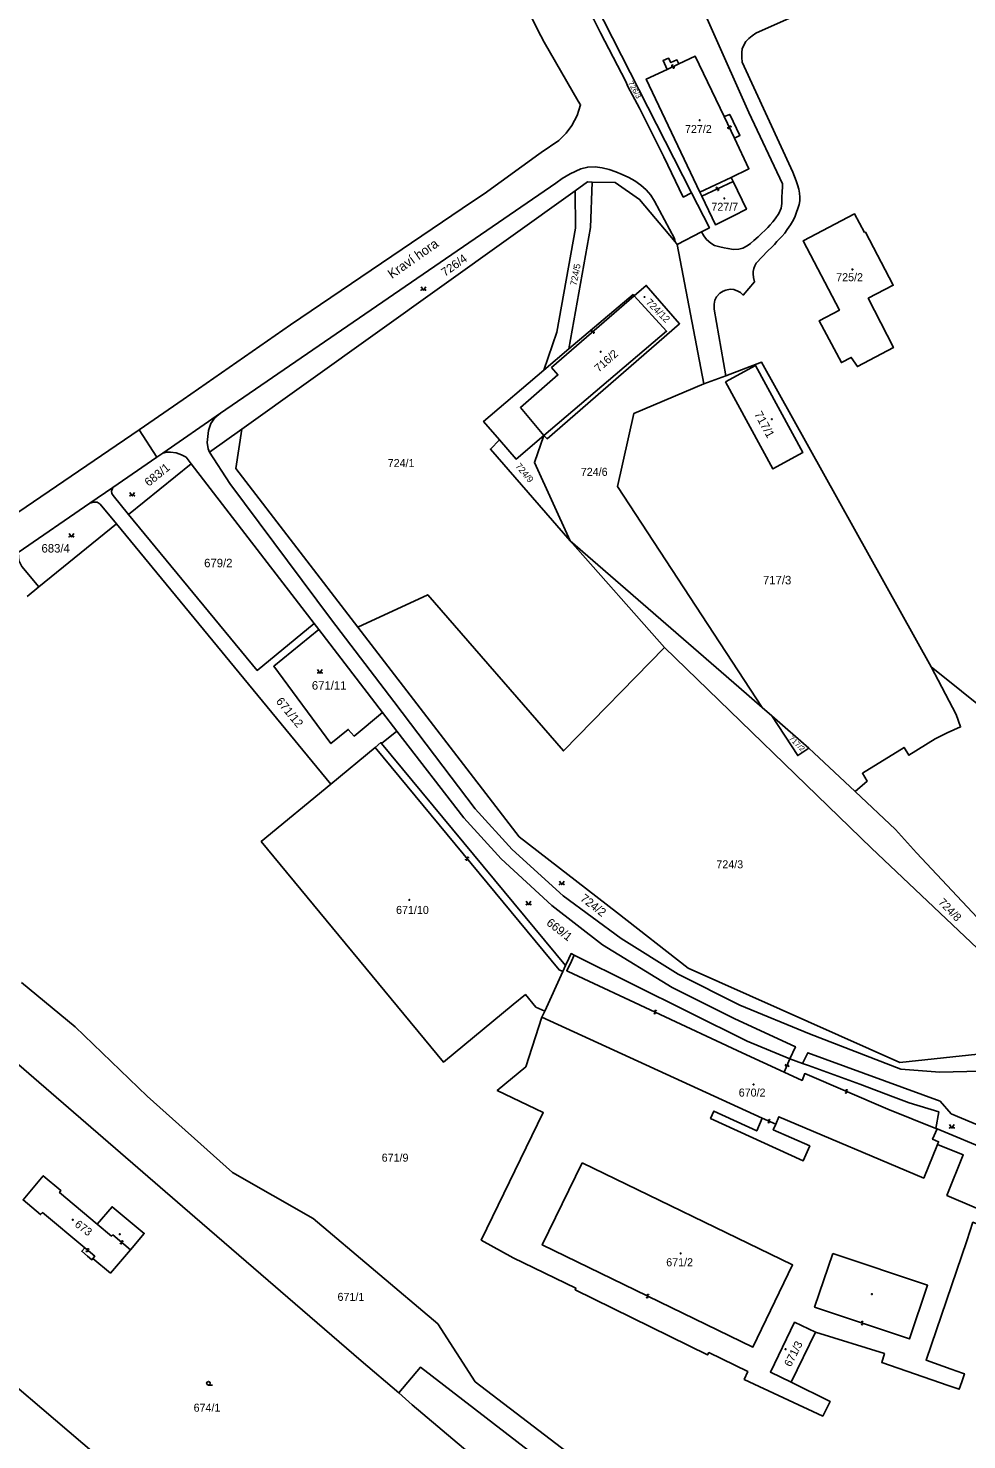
# Model space of a CAD drawing. Extents: x -600391 to -599491, y -1160176 to -1159402.
# Drawn here: x -599792.2 to -599592.8, y -1159973.1 to -1159673.2 of the extents above; entities that cross this region are included whole.
import ezdxf

# ---------------------------------------------------------------- set-up
doc = ezdxf.new("R2010")
doc.units = 0
for name, color, linetype in [('Level 1', 7, 'Continuous'), ('Level 11', 7, 'Continuous'), ('Level 13', 7, 'Continuous'), ('Level 3', 7, 'Continuous'), ('Level 4', 7, 'Continuous'), ('Level 5', 7, 'Continuous')]:
    doc.layers.add(name, color=color, linetype=linetype)

msp = doc.modelspace()

# ---------------------------------------------------------------- linework, layer by layer
at = {"layer": 'Level 1'}
for points in [[(-599712.64, -1159616.57), (-599683.31, -1159674.79), (-599682.57, -1159676.17), (-599675.38, -1159688.67), (-599674.87, -1159689.47), (-599675.56, -1159691.73), (-599676.7, -1159693.85), (-599677.93, -1159695.48), (-599679.49, -1159697.03), (-599683.21, -1159699.58), (-599683.7, -1159699.97), (-599695.31, -1159708.39), (-599697.8, -1159710.05), (-599736.49, -1159736.2), (-599759.29, -1159752.12), (-599768.64, -1159758.53)], [(-599649.16, -1159716.47), (-599648.64, -1159717.29), (-599648.12, -1159718.07), (-599647.22, -1159718.86), (-599646.41, -1159719.36), (-599645.26, -1159719.67), (-599644.38, -1159719.86), (-599643.57, -1159719.98), (-599642.37, -1159720.22), (-599641.27, -1159720.17), (-599640.39, -1159719.92), (-599639.44, -1159719.42), (-599638.77, -1159718.92), (-599638.02, -1159718.29), (-599637.14, -1159717.53), (-599636.39, -1159716.82), (-599635.66, -1159716.1), (-599635.11, -1159715.54), (-599634.57, -1159714.98), (-599634.02, -1159714.36), (-599633.49, -1159713.72), (-599632.75, -1159712.6), (-599632.27, -1159711.41), (-599632.11, -1159710.47), (-599632.07, -1159709.22), (-599632, -1159707.84), (-599631.98, -1159707.06), (-599631.96, -1159706.29), (-599639.09, -1159691.09), (-599669.39, -1159622.91)], [(-599538.78, -1159630.11), (-599637.64, -1159674.26), (-599638.39, -1159674.81), (-599639.14, -1159675.36), (-599639.73, -1159676.01), (-599640.17, -1159676.81), (-599640.5, -1159677.58), (-599640.62, -1159678.37), (-599640.57, -1159679.39), (-599640.53, -1159680.42), (-599629.79, -1159703.81), (-599629.44, -1159704.7), (-599629.09, -1159705.59), (-599628.77, -1159706.48), (-599628.49, -1159707.4), (-599628.33, -1159708.24), (-599628.28, -1159709.09), (-599628.31, -1159709.86), (-599628.44, -1159710.64), (-599628.68, -1159711.47), (-599628.96, -1159712.28), (-599629.28, -1159713.1), (-599629.64, -1159713.91), (-599630.24, -1159714.98), (-599630.95, -1159715.99), (-599631.49, -1159716.72), (-599632.07, -1159717.42), (-599632.61, -1159717.98), (-599633.15, -1159718.54), (-599633.68, -1159719.15), (-599634.23, -1159719.73), (-599635.09, -1159720.48), (-599637.52, -1159723.1), (-599637.85, -1159723.69), (-599638.03, -1159724.24), (-599638.17, -1159724.9), (-599638.18, -1159725.4), (-599638.12, -1159726.14), (-599637.92, -1159727.1), (-599640.3, -1159729.89), (-599640.89, -1159729.34), (-599641.46, -1159729.04), (-599642.32, -1159728.73), (-599643.1, -1159728.65), (-599643.99, -1159728.84), (-599644.57, -1159729.06), (-599645.27, -1159729.51), (-599645.96, -1159730.28), (-599646.32, -1159730.97), (-599646.49, -1159731.85), (-599646.45, -1159732.9), (-599644, -1159747.03)], [(-599677.39, -1159656.98), (-599676.98, -1159659.66), (-599676.42, -1159662.83), (-599672.04, -1159671.33), (-599670.64, -1159674.17), (-599665.22, -1159684.53), (-599664.79, -1159685.6), (-599662.32, -1159690.16), (-599660.1, -1159694.72), (-599657.17, -1159700.54), (-599653.04, -1159709.06), (-599651.27, -1159708.2)], [(-599651.27, -1159708.2), (-599677.39, -1159656.98)], [(-599656.49, -1159681.96), (-599657.33, -1159680.07), (-599656.21, -1159679.54), (-599655.68, -1159680.51), (-599654.38, -1159679.93), (-599653.96, -1159680.76)], [(-599653.96, -1159680.76), (-599650.51, -1159679.17), (-599644.33, -1159691.98)], [(-599656.49, -1159681.96), (-599660.91, -1159684.01), (-599649.52, -1159708)], [(-599644.33, -1159691.98), (-599643.16, -1159691.5), (-599641.01, -1159695.98), (-599642.13, -1159696.53)], [(-599642.13, -1159696.53), (-599639.11, -1159703.04), (-599642.85, -1159704.89)], [(-599751.37, -1159755.02), (-599680.09, -1159706.1), (-599678.78, -1159705.16), (-599677.07, -1159704.13), (-599674.81, -1159703.05), (-599673.32, -1159702.69), (-599671.79, -1159702.68), (-599670.28, -1159702.87), (-599668.82, -1159703.24), (-599667.39, -1159703.7), (-599666, -1159704.26), (-599664.61, -1159704.91), (-599663.32, -1159705.65), (-599662.08, -1159706.53), (-599660.95, -1159707.54), (-599659.95, -1159708.68), (-599659.16, -1159709.97), (-599654.92, -1159717.89), (-599654.76, -1159718.59)], [(-599642.85, -1159704.89), (-599649.52, -1159708)], [(-599642.85, -1159704.89), (-599642.44, -1159705.8)], [(-599746.8, -1159758.36), (-599676.04, -1159707.75)], [(-599676.04, -1159707.75), (-599675.94, -1159715.66), (-599679.93, -1159737.8), (-599682.66, -1159745.87)], [(-599677.33, -1159741.35), (-599672.72, -1159715.52), (-599672.39, -1159705.88)], [(-599672.39, -1159705.88), (-599673.38, -1159705.85), (-599676.04, -1159707.75)], [(-599654.76, -1159718.59), (-599662.33, -1159709.57), (-599667.52, -1159706), (-599672.39, -1159705.88)], [(-599642.44, -1159705.8), (-599639.61, -1159711.67), (-599642.39, -1159713.07), (-599646.21, -1159714.96), (-599649.08, -1159708.89)], [(-599649.16, -1159716.47), (-599647.5, -1159715.59), (-599651.27, -1159708.2)], [(-599649.08, -1159708.89), (-599649.52, -1159708)], [(-599614.56, -1159716.63), (-599614.34, -1159716.51), (-599608.43, -1159727.8), (-599613.75, -1159730.59), (-599608.39, -1159741.06), (-599616.04, -1159745.09), (-599617.37, -1159743.13), (-599619.45, -1159744.23), (-599624.14, -1159735.34), (-599619.87, -1159733.09), (-599627.57, -1159718.38), (-599616.64, -1159712.65), (-599614.56, -1159716.63)], [(-599649.16, -1159716.47), (-599654.31, -1159719.13)], [(-599654.76, -1159718.59), (-599654.31, -1159719.13)], [(-599654.31, -1159719.13), (-599648.64, -1159748.77)], [(-599663.47, -1159730.07), (-599660.9, -1159727.84), (-599653.83, -1159735.98), (-599681.95, -1159760.43), (-599682.65, -1159759.73)], [(-599682.65, -1159759.73), (-599656.58, -1159737.57), (-599663.47, -1159730.07)], [(-599677.33, -1159741.35), (-599663.72, -1159729.8), (-599663.47, -1159730.07)], [(-599682.66, -1159745.87), (-599677.33, -1159741.35)], [(-599682.66, -1159745.87), (-599695.47, -1159756.75), (-599692.07, -1159760.68)], [(-599644.09, -1159748.36), (-599633.99, -1159766.83), (-599627.64, -1159763.35), (-599637.73, -1159744.88), (-599644.09, -1159748.36)], [(-599600.38, -1159808.9), (-599636.39, -1159744.16), (-599644, -1159747.03)], [(-599648.64, -1159748.77), (-599663.55, -1159755.08), (-599667.02, -1159770.59), (-599636.31, -1159817.5)], [(-599648.64, -1159748.77), (-599644, -1159747.03)], [(-599763.62, -1159763.5), (-599751.37, -1159755.02)], [(-599751.37, -1159755.02), (-599752.54, -1159756), (-599753.45, -1159757.22), (-599753.94, -1159758.67), (-599754.18, -1159761.21), (-599754.01, -1159762.59), (-599753.71, -1159763.28)], [(-599768.64, -1159758.53), (-599823.19, -1159795.64), (-599855.6, -1159818.02), (-599902.81, -1159850.42), (-599908.7, -1159854.48)], [(-599764.9, -1159764.36), (-599768.64, -1159758.53)], [(-599753.71, -1159763.28), (-599746.8, -1159758.36)], [(-599746.8, -1159758.36), (-599748.08, -1159766.75), (-599722.17, -1159800.44)], [(-599692.07, -1159760.68), (-599694.03, -1159762.63), (-599677.09, -1159782.15)], [(-599682.65, -1159759.73), (-599688.55, -1159764.75), (-599692.07, -1159760.68)], [(-599677.09, -1159782.15), (-599684.68, -1159765.47), (-599682.65, -1159759.73)], [(-599774.25, -1159770.78), (-599764.9, -1159764.36)], [(-599763.62, -1159763.5), (-599764.9, -1159764.36)], [(-599757.61, -1159765.75), (-599758.68, -1159764.37), (-599759.64, -1159763.82), (-599760.79, -1159763.44), (-599762, -1159763.26), (-599762.83, -1159763.28), (-599763.62, -1159763.5)], [(-599753.71, -1159763.28), (-599749.4, -1159769.94), (-599727.76, -1159798.93), (-599714.51, -1159816.26), (-599697.25, -1159839.07), (-599689.39, -1159847.67), (-599678.59, -1159857.57), (-599666.21, -1159866.59), (-599654.11, -1159874.19), (-599640.99, -1159880.78), (-599626.25, -1159886.88), (-599606.79, -1159894.4), (-599598.5, -1159895.01), (-599584.26, -1159894.68), (-599569.62, -1159897.92), (-599566.09, -1159903.38), (-599555.13, -1159908.18), (-599532.12, -1159913.92), (-599490.77, -1159920.87)], [(-599770.9, -1159776.55), (-599757.61, -1159765.75)], [(-599757.61, -1159765.75), (-599731.47, -1159799.69)], [(-599779.15, -1159774.14), (-599774.25, -1159770.78)], [(-599774.25, -1159770.78), (-599774.51, -1159771.53), (-599774.48, -1159772.05), (-599774.18, -1159772.51), (-599770.9, -1159776.55)], [(-599773.45, -1159778.52), (-599776.9, -1159774.35), (-599777.59, -1159773.93), (-599778.36, -1159773.87), (-599779.15, -1159774.14)], [(-599794.35, -1159784.57), (-599779.15, -1159774.14)], [(-599731.47, -1159799.69), (-599743.54, -1159809.66), (-599770.9, -1159776.55)], [(-599789.93, -1159791.92), (-599773.45, -1159778.52)], [(-599773.45, -1159778.52), (-599727.9, -1159833.79)], [(-599677.09, -1159782.15), (-599641.21, -1159813.22), (-599636.31, -1159817.5)], [(-599677.09, -1159782.15), (-599657.03, -1159804.78)], [(-599794.35, -1159784.57), (-599794.24, -1159786.26), (-599793.56, -1159787.6), (-599789.93, -1159791.92)], [(-599789.93, -1159791.92), (-599792.44, -1159793.96)], [(-599722.17, -1159800.44), (-599707.32, -1159793.57), (-599678.49, -1159826.77), (-599657.03, -1159804.78)], [(-599731.47, -1159799.69), (-599730.48, -1159800.99)], [(-599560.62, -1159898.7), (-599573.09, -1159889.87), (-599573.88, -1159889.45), (-599607.04, -1159892.98), (-599652.03, -1159872.89), (-599667.25, -1159861.02), (-599687.91, -1159844.99), (-599722.17, -1159800.44)], [(-599716.93, -1159818.6), (-599722.98, -1159823.61), (-599724.22, -1159822.19), (-599727.9, -1159825.18), (-599740.04, -1159808.77), (-599730.48, -1159800.99)], [(-599730.48, -1159800.99), (-599716.93, -1159818.6)], [(-599657.03, -1159804.78), (-599613.02, -1159847.44), (-599585.27, -1159873.69), (-599560.62, -1159898.7)], [(-599616.53, -1159835.36), (-599613.95, -1159833.16), (-599614.97, -1159831.49), (-599606.12, -1159826.01), (-599605.11, -1159827.69), (-599599.52, -1159824.22), (-599596.98, -1159822.93), (-599594.14, -1159821.67), (-599595.03, -1159819), (-599600.38, -1159808.9)], [(-599600.38, -1159808.9), (-599587.46, -1159819.24)], [(-599716.93, -1159818.6), (-599713.92, -1159822.53)], [(-599636.31, -1159817.5), (-599634.21, -1159819.33)], [(-599626.37, -1159826.17), (-599628.72, -1159827.73), (-599634.21, -1159819.33)], [(-599626.37, -1159826.17), (-599634.21, -1159819.33)], [(-599717.15, -1159825.18), (-599713.92, -1159822.53)], [(-599713.92, -1159822.53), (-599699.68, -1159840.98), (-599691.72, -1159849.67), (-599680.99, -1159859.58), (-599670.2, -1159867.99), (-599655.4, -1159877.01), (-599642.24, -1159883.59), (-599629.22, -1159889.61), (-599630.38, -1159892.18)], [(-599718.52, -1159826.01), (-599727.9, -1159833.79)], [(-599718.52, -1159826.01), (-599717.3, -1159824.99), (-599717.15, -1159825.18)], [(-599717.15, -1159825.18), (-599678.05, -1159872.37)], [(-599616.53, -1159835.36), (-599625.27, -1159827.13), (-599626.37, -1159826.17)], [(-599727.9, -1159833.79), (-599742.7, -1159846.01), (-599703.97, -1159892.9), (-599689.18, -1159880.66), (-599686.58, -1159878.51), (-599684.35, -1159881.2), (-599682.48, -1159882.05)], [(-599528.47, -1159909.07), (-599547.1, -1159903.06), (-599550.47, -1159897.53), (-599579.75, -1159873.69), (-599603.52, -1159848.43), (-599607.94, -1159843.45), (-599616.53, -1159835.36)], [(-599676.24, -1159870.12), (-599676.87, -1159869.81), (-599677.34, -1159870.83), (-599678.05, -1159872.37)], [(-599678.05, -1159872.37), (-599678.65, -1159873.65)], [(-599676.24, -1159870.12), (-599639.45, -1159888.43), (-599630.38, -1159892.18)], [(-599678.65, -1159873.65), (-599682.48, -1159882.05)], [(-599793.64, -1159875.94), (-599782.21, -1159885.38), (-599766.96, -1159900.14), (-599748.82, -1159916.3), (-599731.65, -1159926.12), (-599705.21, -1159948.48), (-599697.25, -1159960.78), (-599624.79, -1160016.2), (-599608.79, -1160028.24), (-599611.57, -1160032.42)], [(-599683.1, -1159883.34), (-599686.48, -1159893.85), (-599692.58, -1159898.88), (-599682.79, -1159903.6), (-599695.97, -1159930.69), (-599689.19, -1159934.45), (-599675.89, -1159940.9), (-599676.01, -1159941.24), (-599647.86, -1159955.1), (-599647.6, -1159954.59), (-599639.35, -1159958.63), (-599640.1, -1159960.29), (-599623.4, -1159968.09), (-599621.85, -1159964.96), (-599630.11, -1159960.9)], [(-599683.1, -1159883.34), (-599682.48, -1159882.05)], [(-599636.25, -1159904.78), (-599683.1, -1159883.34)], [(-599713.49, -1159963.12), (-599721.48, -1159956.34), (-599756.81, -1159925.79), (-599803.24, -1159885.72)], [(-599578.95, -1159914.46), (-599578.55, -1159911.22), (-599596.11, -1159903.88), (-599598.49, -1159901.19), (-599626.57, -1159890.89), (-599627.69, -1159893.15)], [(-599630.38, -1159892.18), (-599627.69, -1159893.15)], [(-599627.69, -1159893.15), (-599626.47, -1159893.59), (-599615.5, -1159897.57), (-599608.42, -1159900.24), (-599605.02, -1159901.5), (-599598.75, -1159903.46), (-599599.41, -1159906.96)], [(-599633.38, -1159906.06), (-599633.92, -1159907.26), (-599626.16, -1159910.69), (-599627.55, -1159913.85), (-599647.24, -1159904.83), (-599646.56, -1159903.27), (-599637.44, -1159907.5), (-599636.25, -1159904.78)], [(-599599.02, -1159910.35), (-599601.94, -1159917.52), (-599632.72, -1159904.47), (-599633.38, -1159906.06)], [(-599599.02, -1159910.35), (-599598.79, -1159909.79), (-599600.07, -1159909.28), (-599599.13, -1159907.08)], [(-599599.13, -1159907.08), (-599599.41, -1159906.96)], [(-599599.13, -1159907.08), (-599587.58, -1159911.88), (-599578.95, -1159914.46)], [(-599624.96, -1159950.28), (-599610.29, -1159954.8), (-599610.87, -1159956.69), (-599596.78, -1159961.57), (-599594.41, -1159962.38), (-599593.86, -1159960.78), (-599593.31, -1159959.08), (-599593.73, -1159958.98), (-599596.14, -1159958.11), (-599601.47, -1159956.19), (-599592.82, -1159930.88), (-599591.51, -1159926.91), (-599585.94, -1159929.16), (-599584.91, -1159926.39), (-599591.27, -1159923.7), (-599597.04, -1159921.2), (-599593.57, -1159912.61), (-599599.02, -1159910.35)], [(-599780.22, -1159932.33), (-599789.15, -1159924.83), (-599789.59, -1159925.26), (-599793.31, -1159922.15), (-599789.01, -1159917.02), (-599785.28, -1159920.17), (-599785.56, -1159920.58), (-599777.54, -1159927.28)], [(-599777.54, -1159927.28), (-599774.41, -1159923.59), (-599767.57, -1159929.26), (-599770.47, -1159932.73)], [(-599707.8, -1160039.08), (-599761.26, -1159990.41), (-599822.74, -1159937.99), (-599833.95, -1159928.46)], [(-599778.48, -1159934.6), (-599778.69, -1159934.86), (-599779.65, -1159934.1), (-599780.86, -1159933.08), (-599780.22, -1159932.33)], [(-599770.47, -1159932.73), (-599774.75, -1159937.69), (-599778.48, -1159934.6)], [(-599624.96, -1159950.28), (-599629.39, -1159948.15), (-599634.52, -1159958.72), (-599630.11, -1159960.9)], [(-599630.11, -1159960.9), (-599624.96, -1159950.28)], [(-599713.49, -1159963.12), (-599708.86, -1159957.66), (-599667.92, -1159989.3), (-599611.57, -1160032.42)], [(-599713.49, -1159963.12), (-599710.66, -1159965.71), (-599673.85, -1159996.78), (-599702.92, -1160033.44), (-599707.8, -1160039.08)]]:
    msp.add_lwpolyline(points, dxfattribs=at)
at = {"layer": 'Level 13'}
for centre, start, end in [((-599655.3, -1159681.19), 62.7481, 294.8461), ((-599655.14, -1159681.53), 242.5337, 115.1237), ((-599643.4, -1159694.33), 152.9628, 25.5528), ((-599643.06, -1159694.17), 333.1773, 205.2753), ((-599645.84, -1159707.18), 62.1137, 294.7037), ((-599645.68, -1159707.52), 242.3282, 114.4262), ((-599672.37, -1159737.56), 78.3454, 310.4434), ((-599672.13, -1159737.84), 258.131, 130.721), ((-599699.12, -1159849.77), 166.9487, 39.0467), ((-599698.84, -1159849.53), 346.7342, 219.3242), ((-599658.94, -1159882.07), 12.3202, 244.4182), ((-599659.1, -1159882.41), 192.1058, 64.6958), ((-599631.17, -1159893.54), 104.1016, 336.1996), ((-599630.83, -1159893.68), 283.8872, 156.4772), ((-599618.47, -1159899.27), 194.0263, 66.6163), ((-599618.33, -1159898.93), 14.2408, 246.3388), ((-599634.89, -1159905.59), 193.3362, 65.4342), ((-599634.73, -1159905.25), 13.1217, 245.7117), ((-599779.74, -1159932.98), 177.0082, 49.1062), ((-599779.5, -1159932.7), 356.7937, 229.3837), ((-599772.48, -1159931.3), 177.278, 49.868), ((-599772.24, -1159931.02), 357.4925, 229.5905), ((-599660.71, -1159942.75), 191.2734, 63.8634), ((-599660.55, -1159942.41), 11.4878, 243.5858), ((-599615.1, -1159948.49), 198.6296, 71.2196), ((-599614.98, -1159948.15), 18.8441, 250.9421)]:
    msp.add_arc(centre, 0.184, start, end, dxfattribs=at)
at = {"layer": 'Level 3'}
for points in [[(-599656.49, -1159681.96), (-599653.96, -1159680.76)], [(-599644.33, -1159691.98), (-599642.13, -1159696.53)], [(-599642.44, -1159705.8), (-599649.08, -1159708.89)], [(-599682.65, -1159759.73), (-599687.63, -1159753.81), (-599679.68, -1159746.86), (-599681.03, -1159745.32), (-599663.47, -1159730.07)], [(-599678.65, -1159873.65), (-599679.44, -1159873.29), (-599718.52, -1159826.01)], [(-599676.24, -1159870.12), (-599676.82, -1159871.42), (-599677.79, -1159873.45), (-599677.51, -1159873.59), (-599640.52, -1159890.88), (-599631.61, -1159895.04)], [(-599631.61, -1159895.04), (-599630.38, -1159892.18)], [(-599631.61, -1159895.04), (-599627.81, -1159896.78), (-599627.22, -1159895.33), (-599609.57, -1159902.87), (-599599.41, -1159906.96)], [(-599633.38, -1159906.06), (-599636.25, -1159904.78)], [(-599674.54, -1159914.26), (-599683, -1159931.73), (-599638.26, -1159953.44), (-599629.8, -1159935.97), (-599674.54, -1159914.26)], [(-599777.54, -1159927.28), (-599774.49, -1159929.83), (-599774.24, -1159929.58), (-599770.47, -1159932.73)], [(-599778.48, -1159934.6), (-599778.1, -1159934.14), (-599779.02, -1159933.35), (-599780.22, -1159932.33)], [(-599621.3, -1159933.53), (-599625.13, -1159944.94), (-599604.96, -1159951.7), (-599601.14, -1159940.29), (-599621.3, -1159933.53)]]:
    msp.add_lwpolyline(points, dxfattribs=at)
at = {"layer": 'Level 5'}
msp.add_line((-599753.93, -1159961.49), (-599753.06, -1159961.49), dxfattribs=at)
for points in [[(-599708.76, -1159728.12), (-599708.26, -1159728.87), (-599707.76, -1159728.12)], [(-599770.62, -1159771.83), (-599770.12, -1159772.58), (-599769.62, -1159771.83)], [(-599783.54, -1159780.55), (-599783.04, -1159781.3), (-599782.54, -1159780.55)], [(-599730.73, -1159809.49), (-599730.23, -1159810.24), (-599729.73, -1159809.49)], [(-599679.36, -1159854.42), (-599678.86, -1159855.17), (-599678.36, -1159854.42)], [(-599686.41, -1159858.69), (-599685.91, -1159859.44), (-599685.41, -1159858.69)], [(-599596.47, -1159906.15), (-599595.97, -1159906.9), (-599595.47, -1159906.15)]]:
    msp.add_lwpolyline(points, dxfattribs=at)
for centre, radius in [((-599649.56, -1159692.75), 0.09), ((-599649.56, -1159692.75), 0.0521), ((-599644.32, -1159709.36), 0.09), ((-599644.32, -1159709.36), 0.0521), ((-599617.11, -1159724.44), 0.09), ((-599617.11, -1159724.44), 0.0521), ((-599708.71, -1159728.82), 0.05), ((-599707.81, -1159728.82), 0.05), ((-599661.28, -1159730.3), 0.09), ((-599661.28, -1159730.3), 0.0521), ((-599670.59, -1159741.93), 0.09), ((-599670.59, -1159741.93), 0.0521), ((-599634.23, -1159756.27), 0.09), ((-599634.23, -1159756.27), 0.0521), ((-599770.57, -1159772.53), 0.05), ((-599769.67, -1159772.53), 0.05), ((-599783.49, -1159781.25), 0.05), ((-599782.59, -1159781.25), 0.05), ((-599730.68, -1159810.19), 0.05), ((-599729.78, -1159810.19), 0.05), ((-599679.31, -1159855.12), 0.05), ((-599678.41, -1159855.12), 0.05), ((-599711.25, -1159858.41), 0.09), ((-599711.25, -1159858.41), 0.0521), ((-599686.36, -1159859.39), 0.05), ((-599685.46, -1159859.39), 0.05), ((-599638.11, -1159897.63), 0.09), ((-599638.11, -1159897.63), 0.0521), ((-599596.42, -1159906.85), 0.05), ((-599595.52, -1159906.85), 0.05), ((-599782.76, -1159926.37), 0.09), ((-599782.76, -1159926.37), 0.0521), ((-599772.78, -1159929.46), 0.09), ((-599772.78, -1159929.46), 0.0521), ((-599653.6, -1159933.53), 0.09), ((-599653.6, -1159933.53), 0.0521), ((-599612.96, -1159942.16), 0.09), ((-599612.96, -1159942.16), 0.0521), ((-599631.31, -1159953.89), 0.09), ((-599631.31, -1159953.89), 0.0521), ((-599753.93, -1159961.11), 0.375)]:
    msp.add_circle(centre, radius, dxfattribs=at)

# ---------------------------------------------------------------- texts
at = {"layer": 'Level 11'}
msp.add_text('Kraví hora', height=2, rotation=35.0354, dxfattribs=at).set_placement((-599714.95, -1159726.51))
at = {"layer": 'Level 4'}
for s, height, rotation, p in [('726/3', 1.14, 298.8356, (-599664.81, -1159684.82)), ('726/4', 1.8, 35.5737, (-599703.67, -1159726.04)), ('724/5', 1.4, 79.2, (-599675.71, -1159727.98)), ('724/12', 1.5, 315, (-599661.1, -1159731.58)), ('716/2', 1.7, 41.4, (-599670.99, -1159746.38)), ('717/1', 1.8, 298.6713, (-599638.03, -1159755.17)), ('683/1', 1.8, 39.0987, (-599766.6, -1159770.67)), ('724/9', 1.4, 309.6, (-599688.79, -1159766.3)), ('671/12', 1.8, 309.4932, (-599739.7, -1159816.28)), ('717/2', 1.14, 315.8998, (-599630.71, -1159824.23)), ('724/2', 1.8, 322.1923, (-599675.07, -1159858.4)), ('724/8', 1.7, 314.1, (-599598.96, -1159859.04)), ('669/1', 1.8, 322.0663, (-599682.27, -1159863.58)), ('673', 1.7, 323.1, (-599782.49, -1159927.66)), ('671/3', 1.7, 63, (-599630.2, -1159957.77))]:
    msp.add_text(s, height=height, rotation=rotation, dxfattribs=at).set_placement(p)
for s, height, p in [('727/2', 1.7, (-599652.68, -1159695.46)), ('727/7', 1.7, (-599647.07, -1159711.99)), ('725/2', 1.7, (-599620.55, -1159726.95)), ('724/1', 1.7, (-599715.84, -1159766.44)), ('724/6', 1.7, (-599674.81, -1159768.31)), ('683/4', 1.8, (-599789.4, -1159784.6)), ('679/2', 1.8, (-599754.84, -1159787.73)), ('717/3', 1.8, (-599636.11, -1159791.36)), ('671/11', 1.8, (-599731.96, -1159813.74)), ('724/3', 1.7, (-599646.01, -1159851.7)), ('671/10', 1.7, (-599714.06, -1159861.39)), ('670/2', 1.7, (-599641.26, -1159900.2)), ('671/9', 1.7, (-599717.12, -1159914.03)), ('671/2', 1.7, (-599656.66, -1159936.25)), ('671/1', 1.7, (-599726.5, -1159943.61)), ('674/1', 1.7, (-599757.08, -1159967.15))]:
    msp.add_text(s, height=height, dxfattribs=at).set_placement(p)

doc.saveas('drawing.dxf')
